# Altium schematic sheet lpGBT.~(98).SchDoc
size C
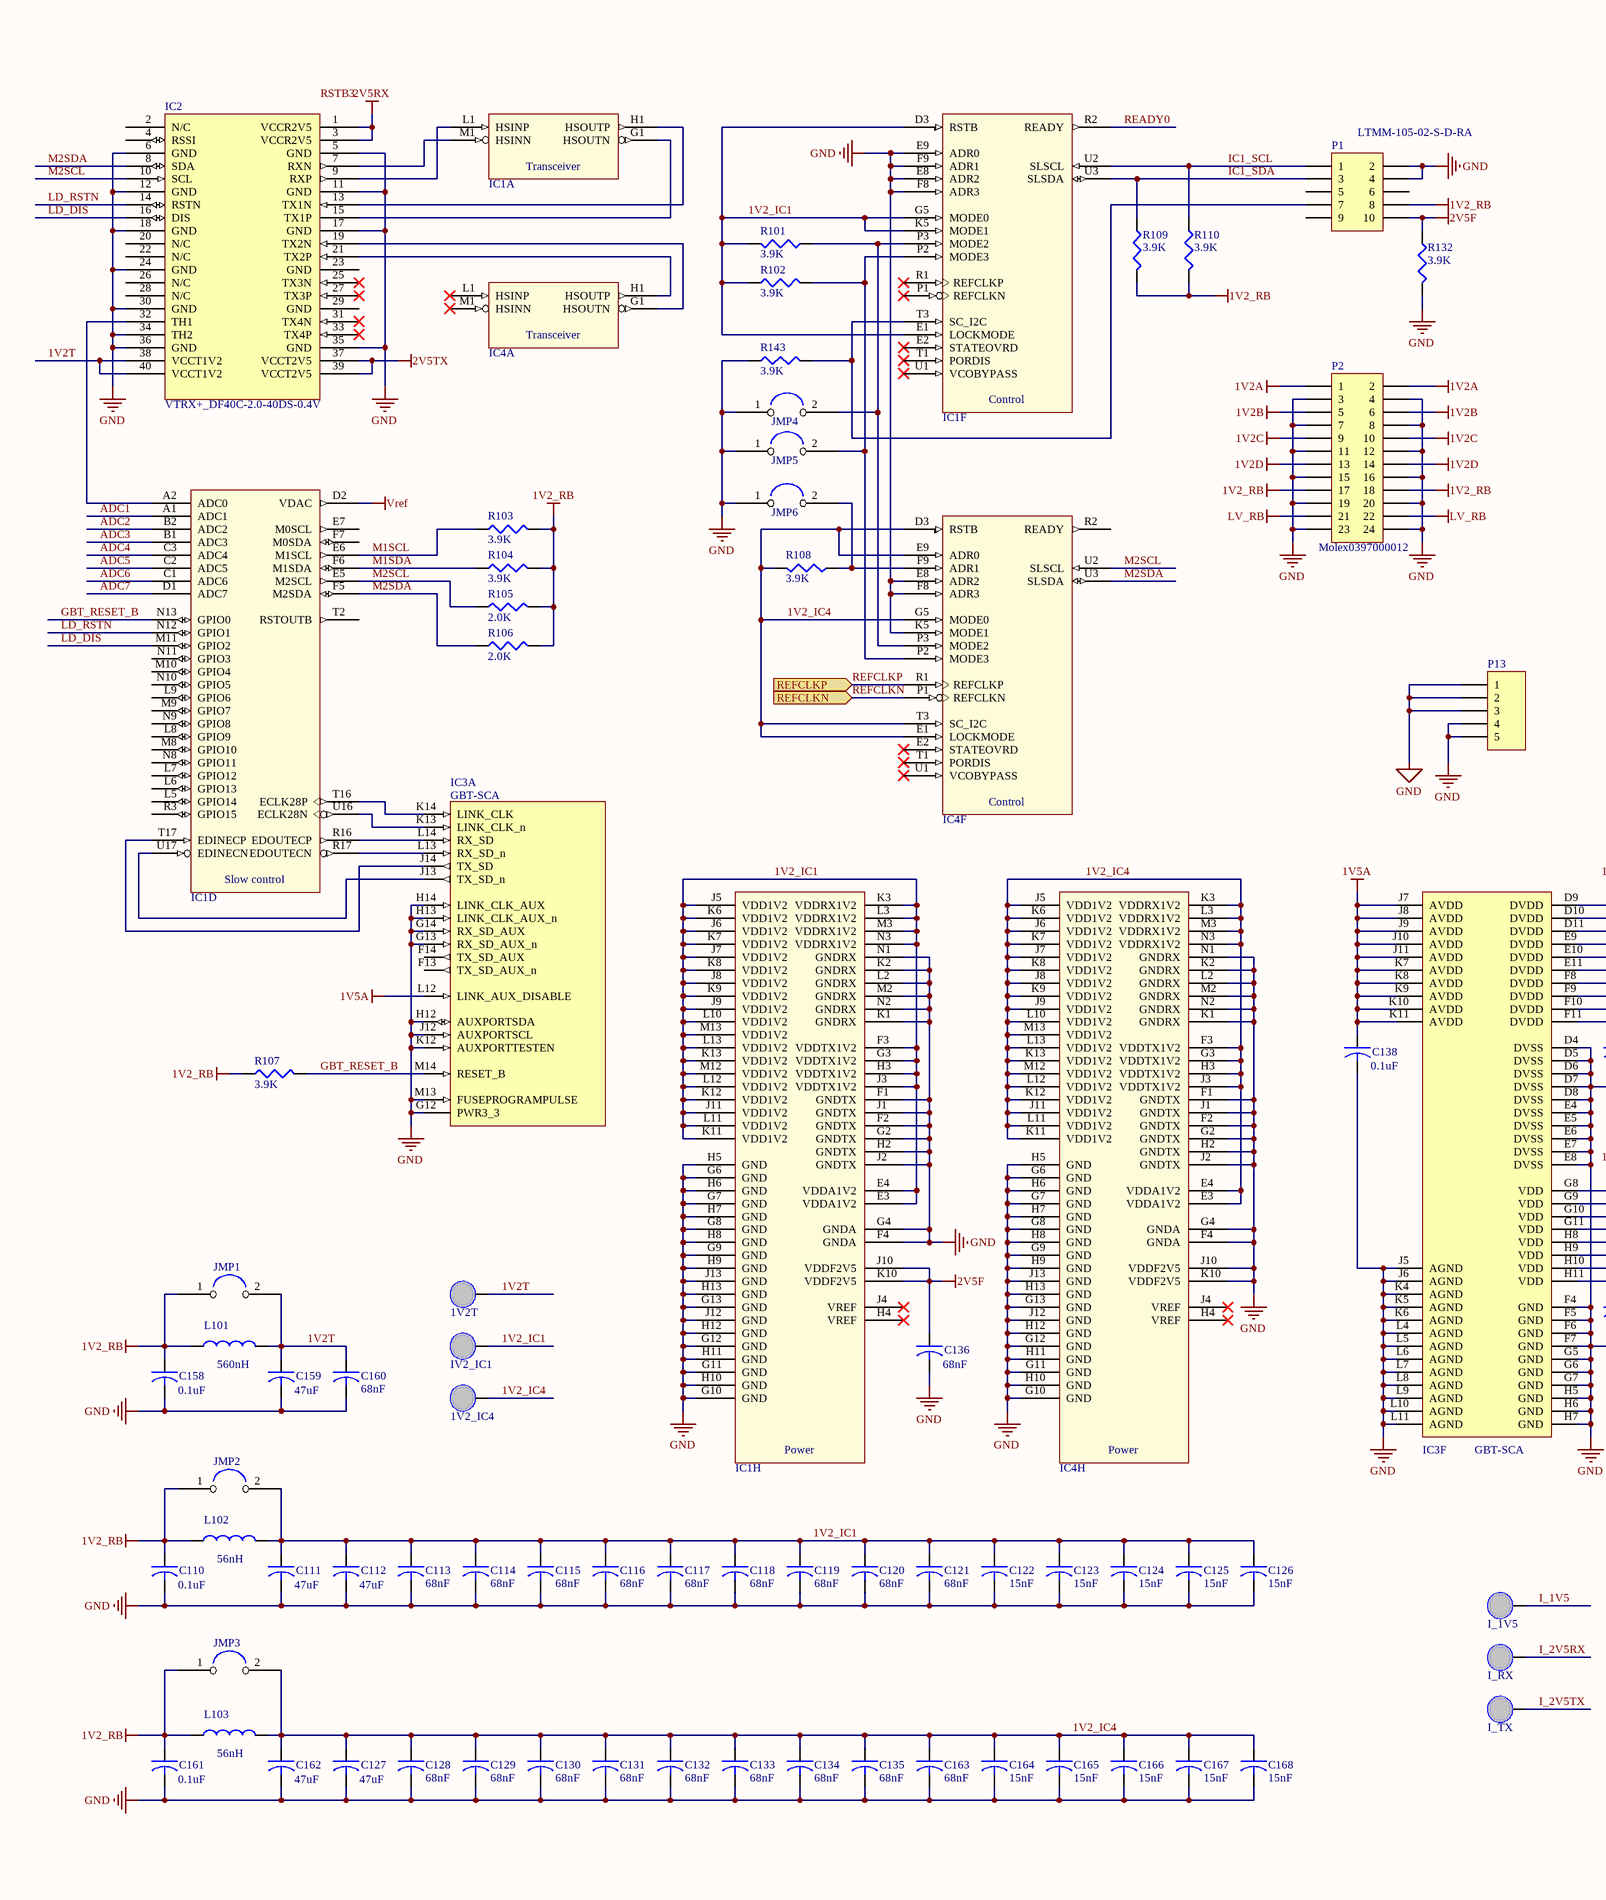
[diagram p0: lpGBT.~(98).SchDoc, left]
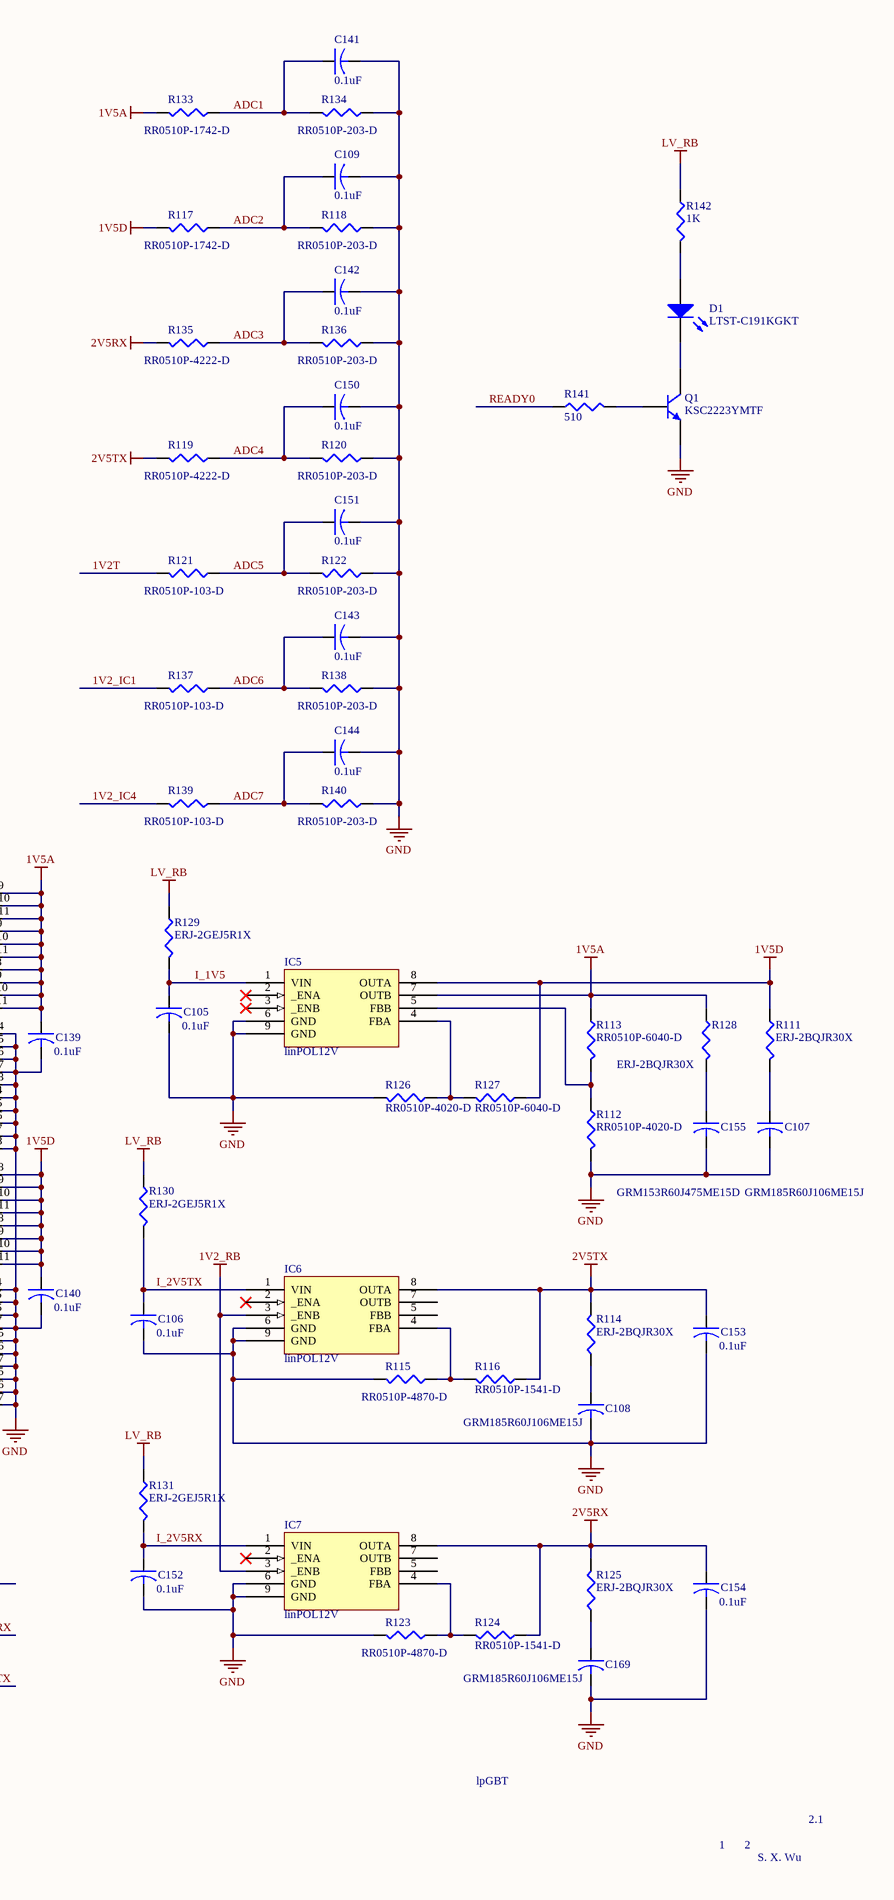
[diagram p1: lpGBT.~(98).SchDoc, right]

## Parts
C105  0.1uF  [capc1005n]
C106  0.1uF  [capc1005n]
C107  GRM185R60J106ME15J  [CAPC1608N]
C108  GRM185R60J106ME15J  [CAPC1608N]
C109  0.1uF  [capc1005n]
C110  0.1uF  [capc1005n]
C111  value 47uF  [capc2012n]  (hidden comment: GRM188R60J476ME15D)
C112  value 47uF  [capc2012n]  (hidden comment: GRM188R60J476ME15D)
C113  value 68nF  [capc1005n]  (hidden comment: GRM033R61C683KE84D)
C114  value 68nF  [capc1005n]  (hidden comment: GRM033R61C683KE84D)
C115  value 68nF  [capc1005n]  (hidden comment: GRM033R61C683KE84D)
C116  value 68nF  [capc1005n]  (hidden comment: GRM033R61C683KE84D)
C117  value 68nF  [capc1005n]  (hidden comment: GRM033R61C683KE84D)
C118  value 68nF  [capc1005n]  (hidden comment: GRM033R61C683KE84D)
C119  value 68nF  [capc1005n]  (hidden comment: GRM033R61C683KE84D)
C120  value 68nF  [capc1005n]  (hidden comment: GRM033R61C683KE84D)
C121  value 68nF  [capc1005n]  (hidden comment: GRM033R61C683KE84D)
C122  15nF  [capc1005n]
C123  15nF  [capc1005n]
C124  15nF  [capc1005n]
C125  15nF  [capc1005n]
C126  15nF  [capc1005n]
C127  value 47uF  [capc2012n]  (hidden comment: GRM188R60J476ME15D)
C128  value 68nF  [capc1005n]  (hidden comment: GRM033R61C683KE84D)
C129  value 68nF  [capc1005n]  (hidden comment: GRM033R61C683KE84D)
C130  value 68nF  [capc1005n]  (hidden comment: GRM033R61C683KE84D)
C131  value 68nF  [capc1005n]  (hidden comment: GRM033R61C683KE84D)
C132  value 68nF  [capc1005n]  (hidden comment: GRM033R61C683KE84D)
C133  value 68nF  [capc1005n]  (hidden comment: GRM033R61C683KE84D)
C134  value 68nF  [capc1005n]  (hidden comment: GRM033R61C683KE84D)
C135  value 68nF  [capc1005n]  (hidden comment: GRM033R61C683KE84D)
C136  value 68nF  [capc1005n]  (hidden comment: GRM033R61C683KE84D)
C138  0.1uF  [capc1005n]
C139  0.1uF  [capc1005n]
C140  0.1uF  [capc1005n]
C141  0.1uF  [capc1005n]
C142  0.1uF  [capc1005n]
C143  0.1uF  [capc1005n]
C144  0.1uF  [capc1005n]
C150  0.1uF  [capc1005n]
C151  0.1uF  [capc1005n]
C152  0.1uF  [capc1005n]
C153  0.1uF  [capc1005n]
C154  0.1uF  [capc1005n]
C155  GRM153R60J475ME15D  [capc1005n]
C158  0.1uF  [capc1005n]
C159  value 47uF  [capc2012n]  (hidden comment: GRM188R60J476ME15D)
C160  value 68nF  [capc1005n]  (hidden comment: GRM033R61C683KE84D)
C161  0.1uF  [capc1005n]
C162  value 47uF  [capc2012n]  (hidden comment: GRM188R60J476ME15D)
C163  value 68nF  [capc1005n]  (hidden comment: GRM033R61C683KE84D)
C164  15nF  [capc1005n]
C165  15nF  [capc1005n]
C166  15nF  [capc1005n]
C167  15nF  [capc1005n]
C168  value 15nF  [capc1005n]  (hidden comment: GRM033R61C153KE4)
C169  GRM185R60J106ME15J  [CAPC1608N]
D1  LTST-C191KGKT  [LED_RED]
IC1  LPGBT  [BGA289X17]  (value not drawn)  (parts A,D,F,H of 8)
IC2  VTRX+_DF40C-2.0-40DS-0.4V  [vtrx+]
IC3  GBT-SCA  [bga196x14]  (parts A,F of 6)
IC4  LPGBT  [BGA289X17]  (value not drawn)  (parts A,F,H of 8)
IC5  linPOL12V  [WDFNX208]
IC6  linPOL12V  [WDFNX208]
IC7  linPOL12V  [WDFNX208]
JMP1  Not a component, printed on PCB  [JMP2]  (value not drawn)
JMP2  Not a component, printed on PCB  [JMP2]  (value not drawn)
JMP3  Not a component, printed on PCB  [JMP2]  (value not drawn)
JMP4  Not a component, printed on PCB  [JMP2]  (value not drawn)
JMP5  Not a component, printed on PCB  [JMP2]  (value not drawn)
JMP6  Not a component, printed on PCB  [JMP2]  (value not drawn)
L101  value 560nH  [indc3216n]  (hidden comment: 1206CS561XJEC)
L102  value 56nH  [indc3216n]  (hidden comment: 1206CS560XJEC)
L103  value 56nH  [indc3216n]  (hidden comment: 1206CS560XJEC)
P1  LTMM-105-02-S-D-RA  [HDR2X5 2mm]
P2  Molex0397000012  [Molex0397000012]
P13  Header 5  [DF57-3]  (value not drawn)
Q1  KSC2223YMTF  [SOT-23]
R101  3.9K  [resc1005n]
R102  3.9K  [resc1005n]
R103  3.9K  [resc1005n]
R104  3.9K  [resc1005n]
R105  2.0K  [resc1005n]
R106  2.0K  [resc1005n]
R107  3.9K  [resc1005n]
R108  3.9K  [resc1005n]
R109  3.9K  [resc1005n]
R110  3.9K  [resc1005n]
R111  ERJ-2BQJR30X  [resc1005n]
R112  RR0510P-4020-D  [resc1005n]
R113  RR0510P-6040-D  [resc1005n]
R114  ERJ-2BQJR30X  [resc1005n]
R115  RR0510P-4870-D  [resc1005n]
R116  RR0510P-1541-D  [resc1005n]
R117  RR0510P-1742-D  [resc1005n]
R118  RR0510P-203-D  [resc1005n]
R119  RR0510P-4222-D  [resc1005n]
R120  RR0510P-203-D  [resc1005n]
R121  RR0510P-103-D  [resc1005n]
R122  RR0510P-203-D  [resc1005n]
R123  RR0510P-4870-D  [resc1005n]
R124  RR0510P-1541-D  [resc1005n]
R125  ERJ-2BQJR30X  [resc1005n]
R126  RR0510P-4020-D  [resc1005n]
R127  RR0510P-6040-D  [resc1005n]
R128  ERJ-2BQJR30X  [resc1005n]
R129  ERJ-2GEJ5R1X  [resc1005n]
R130  ERJ-2GEJ5R1X  [resc1005n]
R131  ERJ-2GEJ5R1X  [resc1005n]
R132  3.9K  [resc1005n]
R133  RR0510P-1742-D  [resc1005n]
R134  RR0510P-203-D  [resc1005n]
R135  RR0510P-4222-D  [resc1005n]
R136  RR0510P-203-D  [resc1005n]
R137  RR0510P-103-D  [resc1005n]
R138  RR0510P-203-D  [resc1005n]
R139  RR0510P-103-D  [resc1005n]
R140  RR0510P-203-D  [resc1005n]
R141  510  [resc1005n]
R142  1K  [resc1005n]
R143  3.9K  [resc1005n]
TP12  1V2T  [testpoint]
TP13  IV2_IC1  [testpoint]
TP14  1V2_IC4  [testpoint]
TP15  I_1V5  [testpoint]
TP16  I_RX  [testpoint]
TP17  I_TX  [testpoint]

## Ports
REFCLKN (in), REFCLKP (in)

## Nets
1V2_RB: C110.1 C158.1 C161.1 IC6.3(_ENB) IC7.3(_ENB) JMP1.1 JMP2.1 JMP3.1 L101.1 L102.1 L103.1 P1.8 P2.17 P2.18 R103.2 R104.2 R105.2 R106.2 R107.1 R109.2 R110.2
1V2A: P2.1 P2.2
1V2B: P2.5 P2.6
1V2C: P2.9 P2.10
1V2D: P2.13 P2.14
1V5A: C138.1 C139.1 IC3.D9(DVDD) IC3.D10(DVDD) IC3.D11(DVDD) IC3.E9(DVDD) IC3.E10(DVDD) IC3.E11(DVDD) IC3.F8(DVDD) IC3.F9(DVDD) IC3.F10(DVDD) IC3.F11(DVDD) IC3.J7(AVDD) IC3.J8(AVDD) IC3.J9(AVDD) IC3.J10(AVDD) IC3.J11(AVDD) IC3.K7(AVDD) IC3.K8(AVDD) IC3.K9(AVDD) IC3.K10(AVDD) IC3.K11(AVDD) IC3.L12(LINK_AUX_DISABLE) IC5.7(OUTB) R113.1 R128.1 R133.2
1V5D: C140.1 IC3.G8(VDD) IC3.G9(VDD) IC3.G10(VDD) IC3.G11(VDD) IC3.H8(VDD) IC3.H9(VDD) IC3.H10(VDD) IC3.H11(VDD) IC5.8(OUTA) R111.1 R117.2 R127.1
2V5F: C136.1 IC1.J10(VDDF2V5) IC1.K10(VDDF2V5) P1.10 R132.1
2V5RX: C154.1 IC2.1(VCCR2V5) IC2.3(VCCR2V5) IC7.8(OUTA) R124.1 R125.2 R135.2
2V5TX: C153.1 IC2.37(VCCT2V5) IC2.39(VCCT2V5) IC6.8(OUTA) R114.2 R116.1 R119.2
GND: C105.2 C106.2 C107.2 C108.2 C109.2 C110.2 C111.2 C112.2 C113.2 C114.2 C115.2 C116.2 C117.2 C118.2 C119.2 C120.2 C121.2 C122.2 C123.2 C124.2 C125.2 C126.2 C127.2 C128.2 C129.2 C130.2 C131.2 C132.2 C133.2 C134.2 C135.2 C136.2 C138.2 C139.2 C140.2 C141.2 C142.2 C143.2 C144.2 C150.2 C151.2 C152.2 C153.2 C154.2 C155.2 C158.2 C159.2 C160.2 C161.2 C162.2 C163.2 C164.2 C165.2 C166.2 C167.2 C168.2 C169.2 IC1.E8(ADR2) IC1.E9(ADR0) IC1.F1(GNDTX) IC1.F2(GNDTX) IC1.F4(GNDA) IC1.F8(ADR3) IC1.F9(ADR1) IC1.G2(GNDTX) IC1.G4(GNDA) IC1.G6(GND) IC1.G7(GND) IC1.G8(GND) IC1.G9(GND) IC1.G10(GND) IC1.G11(GND) IC1.G12(GND) IC1.G13(GND) IC1.H2(GNDTX) IC1.H5(GND) IC1.H6(GND) IC1.H7(GND) IC1.H8(GND) IC1.H9(GND) IC1.H10(GND) IC1.H11(GND) IC1.H12(GND) IC1.H13(GND) IC1.J1(GNDTX) IC1.J2(GNDTX) IC1.J12(GND) IC1.J13(GND) IC1.K1(GNDRX) IC1.K2(GNDRX) IC1.L2(GNDRX) IC1.M2(GNDRX) IC1.N1(GNDRX) IC1.N2(GNDRX) IC2.5(GND) IC2.6(GND) IC2.11(GND) IC2.12(GND) IC2.17(GND) IC2.18(GND) IC2.24(GND) IC2.30(GND) IC2.34(TH2) IC2.35(GND) IC2.36(GND) IC3.D4(DVSS) IC3.D5(DVSS) IC3.D6(DVSS) IC3.D7(DVSS) IC3.D8(DVSS) IC3.E4(DVSS) IC3.E5(DVSS) IC3.E6(DVSS) IC3.E7(DVSS) IC3.E8(DVSS) IC3.F4(GND) IC3.F5(GND) IC3.F6(GND) IC3.F7(GND) IC3.G5(GND) IC3.G6(GND) IC3.G7(GND) IC3.G12(PWR3_3) IC3.G13(RX_SD_AUX_n) IC3.G14(RX_SD_AUX) IC3.H5(GND) IC3.H6(GND) IC3.H7(GND) IC3.H12(AUXPORTSDA) IC3.H13(LINK_CLK_AUX_n) IC3.H14(LINK_CLK_AUX) IC3.J5(AGND) IC3.J6(AGND) IC3.J12(AUXPORTSCL) IC3.K4(AGND) IC3.K5(AGND) IC3.K6(AGND) IC3.K12(AUXPORTTESTEN) IC3.L4(AGND) IC3.L5(AGND) IC3.L6(AGND) IC3.L7(AGND) IC3.L8(AGND) IC3.L9(AGND) IC3.L10(AGND) IC3.L11(AGND) IC3.M13(FUSEPROGRAMPULSE) IC4.E8(ADR2) IC4.F1(GNDTX) IC4.F2(GNDTX) IC4.F4(GNDA) IC4.F8(ADR3) IC4.G2(GNDTX) IC4.G4(GNDA) IC4.G6(GND) IC4.G7(GND) IC4.G8(GND) IC4.G9(GND) IC4.G10(GND) IC4.G11(GND) IC4.G12(GND) IC4.G13(GND) IC4.H2(GNDTX) IC4.H5(GND) IC4.H6(GND) IC4.H7(GND) IC4.H8(GND) IC4.H9(GND) IC4.H10(GND) IC4.H11(GND) IC4.H12(GND) IC4.H13(GND) IC4.J1(GNDTX) IC4.J2(GNDTX) IC4.J10(VDDF2V5) IC4.J12(GND) IC4.J13(GND) IC4.K1(GNDRX) IC4.K2(GNDRX) IC4.K5(MODE1) IC4.K10(VDDF2V5) IC4.L2(GNDRX) IC4.M2(GNDRX) IC4.N1(GNDRX) IC4.N2(GNDRX) IC5.6(GND) IC5.9(GND) IC6.6(GND) IC6.9(GND) IC7.6(GND) IC7.9(GND) JMP4.1 JMP5.1 JMP6.1 P1.2 P1.4 P2.3 P2.4 P2.7 P2.8 P2.11 P2.12 P2.15 P2.16 P2.19 P2.20 P2.23 P2.24 P13.1 P13.2 P13.3 P13.4 P13.5 Q1.3(E) R112.2 R115.2 R118.1 R120.1 R122.1 R123.2 R126.2 R132.2 R134.1 R136.1 R138.1 R140.1 R143.1
LV_RB: P2.21 P2.22 R129.1 R130.1 R131.1 R142.1
Vref: IC1.D2(VDAC)
1V2_IC1: C111.1 C112.1 C113.1 C114.1 C115.1 C116.1 C117.1 C118.1 C119.1 C120.1 C121.1 C122.1 C123.1 C124.1 C125.1 C126.1 IC1.D3(RSTB) IC1.E1(LOCKMODE) IC1.E3(VDDA1V2) IC1.E4(VDDA1V2) IC1.F3(VDDTX1V2) IC1.G3(VDDTX1V2) IC1.G5(MODE0) IC1.H3(VDDTX1V2) IC1.J3(VDDTX1V2) IC1.J5(VDD1V2) IC1.J6(VDD1V2) IC1.J7(VDD1V2) IC1.J8(VDD1V2) IC1.J9(VDD1V2) IC1.J11(VDD1V2) IC1.K3(VDDRX1V2) IC1.K5(MODE1) IC1.K6(VDD1V2) IC1.K7(VDD1V2) IC1.K8(VDD1V2) IC1.K9(VDD1V2) IC1.K11(VDD1V2) IC1.K12(VDD1V2) IC1.K13(VDD1V2) IC1.L3(VDDRX1V2) IC1.L10(VDD1V2) IC1.L11(VDD1V2) IC1.L12(VDD1V2) IC1.L13(VDD1V2) IC1.M3(VDDRX1V2) IC1.M12(VDD1V2) IC1.M13(VDD1V2) IC1.N3(VDDRX1V2) JMP2.2 L102.2 R101.2 R102.1 R137.2 TP13.1(TP)
1V2_IC4: C127.1 C128.1 C129.1 C130.1 C131.1 C132.1 C133.1 C134.1 C135.1 C162.1 C163.1 C164.1 C165.1 C166.1 C167.1 C168.1 IC4.D3(RSTB) IC4.E1(LOCKMODE) IC4.E3(VDDA1V2) IC4.E4(VDDA1V2) IC4.E9(ADR0) IC4.F3(VDDTX1V2) IC4.G3(VDDTX1V2) IC4.G5(MODE0) IC4.H3(VDDTX1V2) IC4.J3(VDDTX1V2) IC4.J5(VDD1V2) IC4.J6(VDD1V2) IC4.J7(VDD1V2) IC4.J8(VDD1V2) IC4.J9(VDD1V2) IC4.J11(VDD1V2) IC4.K3(VDDRX1V2) IC4.K6(VDD1V2) IC4.K7(VDD1V2) IC4.K8(VDD1V2) IC4.K9(VDD1V2) IC4.K11(VDD1V2) IC4.K12(VDD1V2) IC4.K13(VDD1V2) IC4.L3(VDDRX1V2) IC4.L10(VDD1V2) IC4.L11(VDD1V2) IC4.L12(VDD1V2) IC4.L13(VDD1V2) IC4.M3(VDDRX1V2) IC4.M12(VDD1V2) IC4.M13(VDD1V2) IC4.N3(VDDRX1V2) IC4.T3(SC_I2C) JMP3.2 L103.2 R108.2 R139.2 TP14.1(TP)
1V2T: C159.1 C160.1 IC2.38(VCCT1V2) IC2.40(VCCT1V2) JMP1.2 L101.2 R121.2 TP12.1(TP)
ADC1: C141.1 IC1.A1(ADC1) R133.1 R134.2
ADC2: C109.1 IC1.B2(ADC2) R117.1 R118.2
ADC3: C142.1 IC1.B1(ADC3) R135.1 R136.2
ADC4: C150.1 IC1.C3(ADC4) R119.1 R120.2
ADC5: C151.1 IC1.C2(ADC5) R121.1 R122.2
ADC6: C143.1 IC1.C1(ADC6) R137.1 R138.2
ADC7: C144.1 IC1.D1(ADC7) R139.1 R140.2
GBT_RESET_B: IC1.N13(GPIO0) IC3.M14(RESET_B) R107.2
I_1V5: C105.1 IC5.1(VIN) R129.2 TP15.1(TP)
I_2V5RX: C152.1 IC7.1(VIN) R131.2 TP16.1(TP)
I_2V5TX: C106.1 IC6.1(VIN) R130.2 TP17.1(TP)
IC1_SCL: IC1.U2(SLSCL) P1.1 R110.1
IC1_SDA: IC1.U3(SLSDA) P1.3 R109.1
LD_DIS: IC1.M11(GPIO2) IC2.16(DIS)
LD_RSTN: IC1.N12(GPIO1) IC2.14(RSTN)
M1SCL: IC1.E6(M1SCL) R103.1
M1SDA: IC1.F6(M1SDA) R104.1
M2SCL: IC1.E5(M2SCL) IC2.10(SCL) IC4.U2(SLSCL) R105.1
M2SDA: IC1.F5(M2SDA) IC2.8(SDA) IC4.U3(SLSDA) R106.1
READY0: IC1.R2(READY) R141.1
REFCLKN: IC4.P1(REFCLKN) ; port REFCLKN
REFCLKP: IC4.R1(REFCLKP) ; port REFCLKP
NetC107_1: C107.1 R111.2
NetC108_1: C108.1 R114.1
NetC155_1: C155.1 R128.2
NetC169_1: C169.1 R125.1
NetD1_1: D1.1(A) R142.2
NetD1_2: D1.2(K) Q1.1(C)
NetIC1_A2: IC1.A2(ADC0) IC2.32(TH1)
NetIC1_G1: IC1.G1(HSOUTN) IC2.15(TX1P)
NetIC1_H1: IC1.H1(HSOUTP) IC2.13(TX1N)
NetIC1_L1: IC1.L1(HSINP) IC2.9(RXP)
NetIC1_M1: IC1.M1(HSINN) IC2.7(RXN)
NetIC1_P2: IC1.P2(MODE3) IC4.P2(MODE3) JMP5.2 R102.2
NetIC1_P3: IC1.P3(MODE2) IC4.P3(MODE2) JMP4.2 R101.1
NetIC1_R16: IC1.R16(EDOUTECP) IC3.L14(RX_SD)
NetIC1_R17: IC1.R17(EDOUTECN) IC3.L13(RX_SD_n)
NetIC1_T3: IC1.T3(SC_I2C) P1.7 R143.2
NetIC1_T16: IC1.T16(ECLK28P) IC3.K14(LINK_CLK)
NetIC1_T17: IC1.T17(EDINECP) IC3.J14(TX_SD)
NetIC1_U16: IC1.U16(ECLK28N) IC3.K13(LINK_CLK_n)
NetIC1_U17: IC1.U17(EDINECN) IC3.J13(TX_SD_n)
NetIC2_19: IC2.19(TX2N) IC4.G1(HSOUTN)
NetIC2_21: IC2.21(TX2P) IC4.H1(HSOUTP)
NetIC4_F9: IC4.F9(ADR1) JMP6.2 R108.1
NetIC5_4: IC5.4(FBA) R126.1 R127.2
NetIC5_5: IC5.5(FBB) R112.1 R113.2
NetIC6_4: IC6.4(FBA) R115.1 R116.2
NetIC7_4: IC7.4(FBA) R123.1 R124.2
NetQ1_2: Q1.2(B) R141.2

Not connected (* = marked no-connect by the designer): IC1 E2(STATEOVRD)* E7(M0SCL) F7(M0SDA) H4(VREF)* J4(VREF)* L5(GPIO14) L6(GPIO13) L7(GPIO12) L8(GPIO9) L9(GPIO6) M8(GPIO10) M9(GPIO7) M10(GPIO4) N8(GPIO11) N9(GPIO8) N10(GPIO5) N11(GPIO3) P1(REFCLKN)* R1(REFCLKP)* R3(GPIO15) T1(PORDIS)* T2(RSTOUTB) U1(VCOBYPASS)*; IC2 2(N/C) 4(RSSI) 20(N/C) 22(N/C) 23(GND) 25(TX3N)* 26(N/C) 27(TX3P)* 28(N/C) 29(GND) 31(TX4N)* 33(TX4P)*; IC3 F13(TX_SD_AUX_n) F14(TX_SD_AUX); IC4 E2(STATEOVRD)* H4(VREF)* J4(VREF)* L1(HSINP)* M1(HSINN)* R2(READY) T1(PORDIS)* U1(VCOBYPASS)*; IC5 2(_ENA)* 3(_ENB)*; IC6 2(_ENA)* 5(FBB) 7(OUTB); IC7 2(_ENA)* 5(FBB) 7(OUTB); P1 5 6 9

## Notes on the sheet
- lpGBT
- 1
- 2
- S. X. Wu
- 2.1
- Labels drawn without touching a wire or pin: RSTB3

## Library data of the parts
C105 C106 C109-C136 C138-C144 C150-C154 C158-C168 = C: CERAMIC CAPACITOR
C107 C108 C169 = C: CERAMIC CAPACITOR; VALUE: 10uF
C155 = C: CERAMIC CAPACITOR; VALUE: 4.7uF
D1 = LED2: Typical RED, GREEN, YELLOW, AMBER GaAs LED
IC1 IC4 = LPGBT: Low Power Gigabit Transceiver; Manufacturer: CERN; Pinout Version: 180226; Bonding: No
IC2 = VTRX+_DF40C-2.0-40DS-0.4V: VTRX+ module with 2.5mm stack Height.
IC3 = CERN_GBT-SCA_REV 6.2: The Slow Control Adapter ASIC for the GBT System
JMP1-JMP6 = JMP2: printed on PCB
L101-L103 = INDUCTOR: POWER INDUCTOR
P1 = Header 5X2: Header, 5-Pin, Dual row 2mm pitch
P2 = Header 12X2: Header, 12-Pin, Dual row
P13 = Header 5: Header, 5-Pin
Q1 = NPN: NPN Bipolar Transistor
R101-R143 = R1: FILM RESISTOR; Text Field2: 1%
TP12-TP17 = TP: TEST POINT 40MIL DIA.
